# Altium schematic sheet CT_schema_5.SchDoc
size 218 x 258 mm
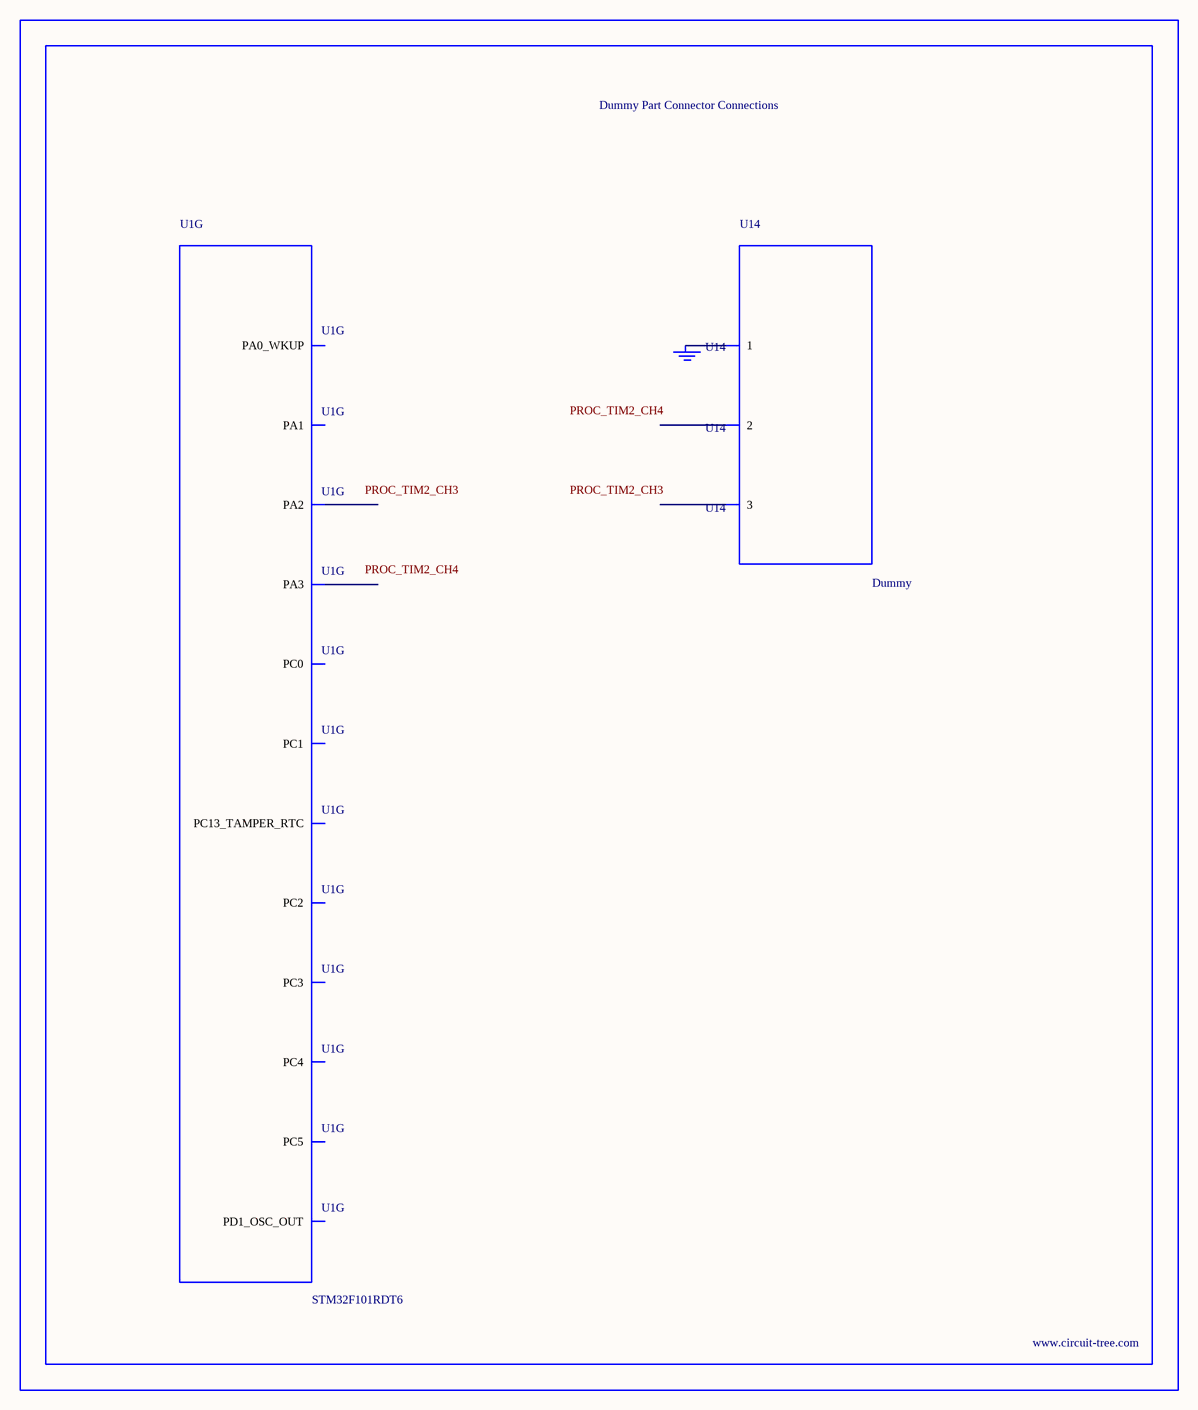
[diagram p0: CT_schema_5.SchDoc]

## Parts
BORDER4  (no value)
GND_INSTANCE_4_0  (no value)
U1  STM32F101RDT6  [LQFP64]  (part G of 7)
U14  Dummy  [DUMMY_PACKAGE_134]

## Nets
NetGND_INSTANCE_4_0_0: GND_INSTANCE_4_0.0(GND) U14.1

Not connected (* = marked no-connect by the designer): U1 2(PC13_TAMPER_RTC) 6(PD1_OSC_OUT) 8(PC0) 9(PC1) 10(PC2) 11(PC3) 14(PA0_WKUP) 15(PA1) 16(PA2) 17(PA3) 24(PC4) 25(PC5); U14 2 3

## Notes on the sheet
- Labels drawn without touching a wire or pin: PROC_TIM2_CH3, PROC_TIM2_CH4

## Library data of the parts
BORDER4 = BORDER_PAGE4
GND_INSTANCE_4_0 = GND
